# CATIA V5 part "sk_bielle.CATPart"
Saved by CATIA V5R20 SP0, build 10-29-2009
Part number: sk_bielle
Publications: "Point.1", "Point.3", "Droite.1", "Droite.2", "Droite.3", "Plan.1", "Plan.2"
Bounding box of the stored display mesh (mm): x -20 to 20, y 27.953 to 153.743, z 20.891 to 69.9
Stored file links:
  D:\Dropbox\IAO_2011\MMS_GR2\IAO_2011_1495_fpittorino\fpittorino_IAO\IAO_2011_1495_fpittorino\sk_bielle.CATPart
  D:\Dropbox\IAO_2011\MMS_GR2\IAO_2011_1495_fpittorino\fpittorino_IAO\IAO_2011_1495_fpittorino\Product3.CATProduct
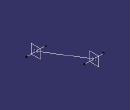
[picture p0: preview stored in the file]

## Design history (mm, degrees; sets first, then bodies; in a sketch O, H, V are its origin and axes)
Set1
  Point1: linked copy from another document
  Point2: linked copy from another document
Body1 (main body)
  Point3: (0, 0, 0), relative to Point1
  Point4: (0, 0, 0), relative to Point2
  Line1: type PtPt, FirstPoint Point3, SecondPoint Point4
  Line2: type Normal, RefPoint Point3, RefSkin yz-plane, Start -20, End 20
  Line3: type Normal, RefPoint Point4, RefSkin yz-plane, Start -20, End 20
  Plane1: type Normal, Curve Line2, RefPoint Point3
  Plane2: type Normal, Curve Line3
